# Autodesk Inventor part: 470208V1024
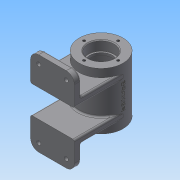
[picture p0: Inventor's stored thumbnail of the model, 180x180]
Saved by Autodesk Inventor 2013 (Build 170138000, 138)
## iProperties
Created: 2017-02
Part Number: 470208V1024
Material: Generic
Document SubType Name: Modeling
Designer: Administrator
Density: 1 g/cm^3
Author: Administrator
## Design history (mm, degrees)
sketch "스케치1"
  geometry: C1 r 27 at (0, 0); 1 further point
  constraints: 1 centre point, 1 coincident
  dimensions: "d0" = 54 diameter of C1
extrude "돌출1" new body sketch "스케치1" stored distance "d1" = 70; taper "d2" = 0 deg
node "작업 평면1"
sketch "스케치2"
  geometry: L1 (27, 17)-(-27, 17); L2 (-27, 17)-(-27, 52); L3 (-27, 52)-(27, 52); L4 (27, 52)-(27, 17); 1 further point
  constraints: 8 end point, 2 parallel, 1 horizontal, 1 perpendicular
  dimensions: "d4" = 17 distance from line of point (0, 0) L1; "d5" = 54 distance of L2.end L3.end; "d6" = 27 distance from line of point (0, 0) L2; "d7" = 35 distance of L1.end L2.end
extrude "돌출2" join sketch "스케치2" distance "d8" = 8; taper "d9" = 0 deg
sketch "스케치3"
  geometry: L1 (-27, -17)-(27, -17); L2 (27, -17)-(27, -25); L3 (27, -25)-(-27, -25); L4 (-27, -25)-(-27, -17); 1 further point
  constraints: 8 end point, 2 parallel, 1 horizontal, 1 perpendicular
  dimensions: "d10" = 54 distance of L2.end L3.end; "d11" = 8 distance of L1.end L2.end
extrude "돌출3" join sketch "스케치3" stored distance "d12" = 8; taper "d13" = 0 deg
sketch "스케치4"
  geometry: C1 r 2.5 at (-17, -42); 1 further point
  constraints: 1 centre point
  dimensions: "d14" = 5 diameter of C1; "d15" = 17 horizontal distance of point (0, 0) C1.centre; "d16" = 42 vertical distance of point (0, 0) C1.centre
extrude "돌출4" cut sketch "스케치4" distance "d17" = 8; taper "d18" = 0 deg
sketch "스케치6"
  geometry: L1 (-12.5, -44.598)-(-17, -47.196); L2 (-17, -47.196)-(-21.5, -44.598); L3 (-21.5, -44.598)-(-21.5, -39.402); L4 (-21.5, -39.402)-(-17, -36.804); L5 (-17, -36.804)-(-12.5, -39.402); L6 (-12.5, -39.402)-(-12.5, -44.598); C1 r 2.5 at (-17, -42) reference; 3 further points
  constraints: 12 end point, 1 midpoint, 13 other
extrude "돌출5" cut sketch "스케치6" distance "d20" = 3; taper "d21" = 0 deg
fillet "모깎기1" dims "d22" = 10
node "작업 평면2"
sketch "스케치7"
  geometry: L1 (27, 35)-(-27, 35) reference; C1 r 5 at (0, 10); 1 further point
  constraints: 1 centre point
  dimensions: "d24" = 10 diameter of C1; "d25" = 25 distance from line of L1 C1.centre
extrude "돌출6" join sketch "스케치7" stored distance "d26" = 3; taper "d27" = 0 deg
sketch "스케치8"
  geometry: C1 r 27 at (0, 0) reference; C2 r 16 at (0, 0)
  constraints: 1 centre point, 1 coincident
  dimensions: "d28" = 32 diameter of C2
extrude "돌출7" cut sketch "스케치8" distance "d29" = 12; taper "d30" = 0 deg
sketch "스케치9"
  geometry: C1 r 16 at (0, 0) reference; C2 r 14 at (0, 0)
  constraints: 1 centre point, 1 coincident
  dimensions: "d31" = 28 diameter of C2
extrude "돌출8" cut sketch "스케치9" distance "d32" = 3; taper "d33" = 0 deg
sketch "스케치10"
  geometry: C1 r 14 at (0, 0) reference; C2 r 22 at (0, 0)
  constraints: 1 centre point, 1 coincident
  dimensions: "d34" = 44 diameter of C2
extrude "돌출9" cut sketch "스케치10" distance "d35" = 40; taper "d36" = 0 deg
hole "구멍1" diameter "d39" = 5.188; stored, may be unused: countersink angle "d43" = 90 deg, drill point angle "d45" = 118 deg; dims "d40" = 30, "d41" = 4, "d42" = 2, "d44" = 30, "d63" = 10, "d64" = 10
node "작업 평면3"
sketch "스케치12"
  geometry: 2 further points
  constraints: 1 coincident, 1 other
feature "엠보싱1" sketch "스케치12" dims "d12" = 8, "d13" = 0, "d47" = 0.5, "d48" = 0
sketch "스케치13"
  geometry: L1 (0, 0)-(-16.339, -25.16); L2 (0, 0)-(30, 0)
  constraints: 4 end point, 1 equal length, 1 horizontal
  dimensions: "d49" = 30 distance of L1.start L1.end; "d50" = 123 deg angle of L1 L2
node "작업 평면4"
sketch "스케치14"
  geometry: C1 r 6 at (0, 0); 1 further point
  constraints: 1 centre point, 1 coincident
  dimensions: "d51" = 12 diameter of C1
extrude "돌출10" join sketch "스케치14" stored distance "d52" = 40; taper "d53" = 0 deg
sketch "스케치15"
  geometry: C1 r 6 at (0, 0) reference
sketch "스케치16"
  geometry: C1 r 6 at (0, 0) reference
hole "구멍2" diameter "d56" = 5.188; stored, may be unused: countersink angle "d60" = 90 deg, drill point angle "d62" = 118 deg; dims "d54" = 10, "d55" = 10, "d57" = 30, "d58" = 4, "d59" = 2, "d61" = 30
sketch "스케치17"
  geometry: L1 (0, 0)-(0, 21); C1 r 27 at (0, 0) reference; 1 further point
  constraints: 2 end point, 1 coincident, 1 vertical
  dimensions: "d65" = 21 distance of L1.start L1.end
hole "구멍3" sketch "스케치17" at (0, 21) diameter "d66" = 3.242; stored, may be unused: countersink angle "d70" = 90 deg, drill point angle "d72" = 118 deg; dims "d67" = 8, "d68" = 4, "d69" = 2, "d71" = 10
fillet "모깎기2" dims "d76" = 10
fillet "모깎기3" dims "d77" = 2
fillet "모깎기4" dims "d78" = 2
fillet "모깎기5" dims "d79" = 2
fillet "모깎기6" dims "d80" = 2
fillet "모깎기7" dims "d81" = 2
fillet "모깎기8" dims "d82" = 0.3
chamfer "모따기1" distance "d83" = 1; stored, may be unused: second distance "d84" = 2, angle "d85" = 45 deg
fillet "모깎기9" dims "d86" = 2
fillet "모깎기10" dims "d87" = 2
fillet "모깎기11" dims "d88" = 3
node "솔리드1"
mirror "대칭1"
mirror "대칭2"
mirror "대칭3"
pattern_circular "원형 패턴1" dims angle "d74" = 360 deg
mirror "대칭4"
other parameters: "d23" = 32, "d46" = 27
